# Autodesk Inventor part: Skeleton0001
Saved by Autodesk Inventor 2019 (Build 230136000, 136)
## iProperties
Created: 2018-04
Part Number: Skeleton0001
Material: 一般
Document SubType Name: Modeling
Designer: shimont
Density: 1 g/cm^3
Appearance: 既定
_SkeletonDoc: Frame Skeleton File
_Version: 15.0.0
Author: shimont
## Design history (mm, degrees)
sketch "参照スケルトン"
